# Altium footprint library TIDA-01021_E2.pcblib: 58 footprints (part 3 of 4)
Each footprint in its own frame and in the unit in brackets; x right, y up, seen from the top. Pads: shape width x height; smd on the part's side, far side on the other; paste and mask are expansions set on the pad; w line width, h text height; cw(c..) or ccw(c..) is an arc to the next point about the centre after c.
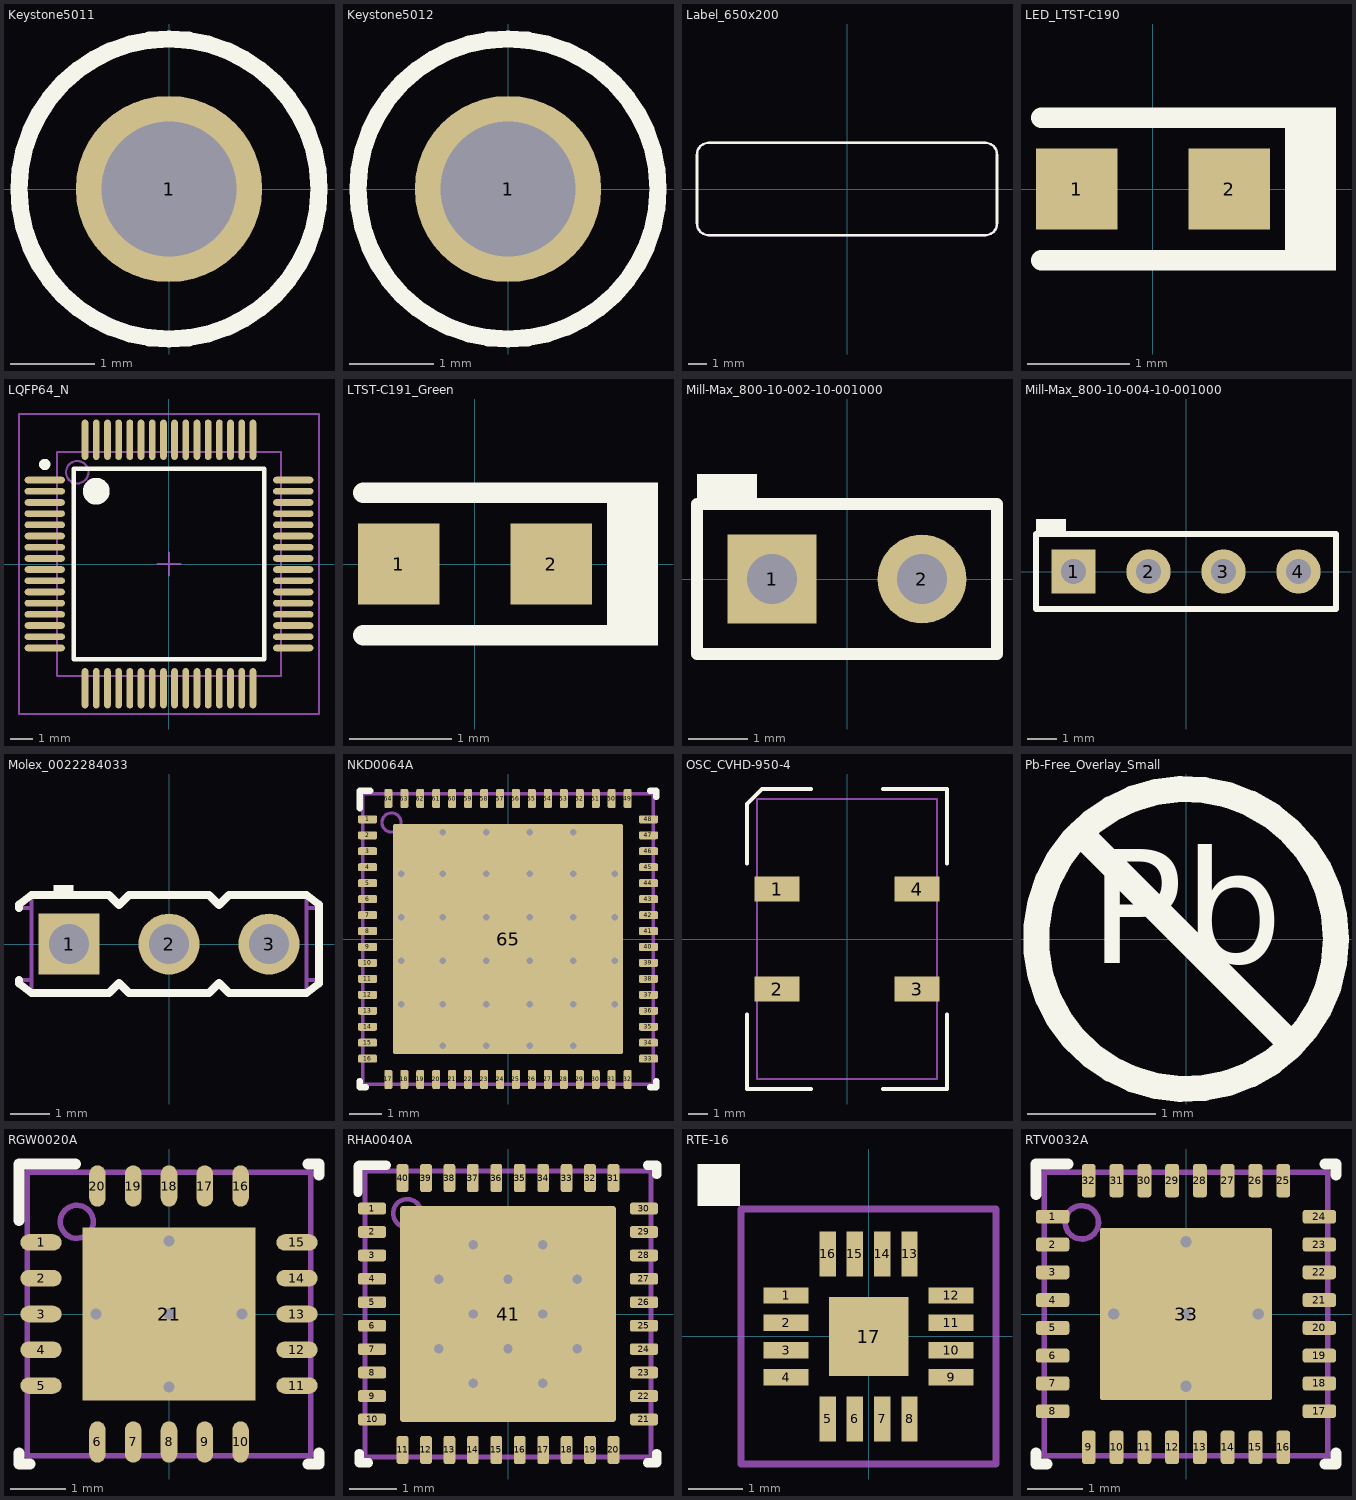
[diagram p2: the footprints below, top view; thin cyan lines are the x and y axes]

## Keystone5011 [mil] "Keystone Multipurpose loops"
height 320
pads (1):
  round 87 hole 63: 1(0,0)
Top Overlay:
  circle w7.99: c0,0 r70
Mechanical 5:
  circle w5: c0,0 r69.46
  text ".Designator" at 9.51,-35.02 h25
3D body "Keystone_5011.stp": height 318.9, standoff -125.98, extent -63,-63 62.74,62.49

## Keystone5012 [mil] "Keystone Multipurpose loops"
height 320
pads (1):
  round 87 hole 63: 1(0,0)
Top Overlay:
  circle w7.99: c0,0 r70
Mechanical 5:
  circle w5: c0,0 r69.46
  text ".Designator" at 37.32,14.4 h25
3D body "Keystone_5012.stp": height 318.9, standoff -125.98, extent -63,-63 62.74,62.49

## Label_650x200 [mil] "Thermal Transfer Label"
height 1
pads (1):
  round 1 on Mech13: 0(0,0)
Top Overlay:
  lines w5: -325,-75 ccw(c-300,-75) -300,-100 ; -325,75 cw(c-300,75) -300,100 ; 300,-100 ccw(c300,-75) 325,-75 ; 300,100 cw(c300,75) 325,75
  lines w6: -325,-75 -325,75 ; -300,-100 300,-100 ; -300,100 300,100 ; 325,-75 325,75
Mechanical 5:
  lines w5: -325,-75 ccw(c-300,-75) -300,-100 300,-100 ccw(c300,-75) 325,-75 325,75 ccw(c300,75) 300,100 -300,100 ccw(c-300,75) -325,75 -325,-75
  text ".Designator" at -60,-20 h25
3D body: height 1, standoff 0, extent -325.02,-100.02 325.02,100.02

## LED_LTST-C190 [mm] "Lite-On"
height 0.9
pads (2):
  rect 0.8x0.8 smd: 1(-0.75,0) 2(0.75,0)
Top Overlay:
  region: 1.8,0.8 1.3,0.8 1.3,-0.8 1.8,-0.8
  lines w0.2: -1.1,-0.7 1.4,-0.7 ; -1.1,0.7 1.4,0.7
Mechanical 5:
  region: 1.8,0.75 1.3,0.75 1.3,-0.75 1.8,-0.75
  lines w0.1: -1.1,-0.7 1.4,-0.7 ; -1.1,0.7 1.4,0.7
  text ".Designator" at 0.802,0.364 h0.64
3D body "Lite-On_LTST_C190.stp": height 0.9, standoff 0, extent -0.85,-0.45 0.85,0.45

## LQFP64_N [mm] "Thin QFP, 64-Leads, Body 10x10mm, Pitch 0.5mm, IPC Medium Density"
height 1.6
pads (64):
  oval 1.8x0.3 smd: 1(-5.55,3.75) 2(-5.55,3.25) 3(-5.55,2.75) 4(-5.55,2.25) 5(-5.55,1.75) 6(-5.55,1.25) 7(-5.55,0.75) 8(-5.55,0.25) 9(-5.55,-0.25) 10(-5.55,-0.75) 11(-5.55,-1.25) 12(-5.55,-1.75) 13(-5.55,-2.25) 14(-5.55,-2.75) 15(-5.55,-3.25) 16(-5.55,-3.75) 33(5.55,-3.75) 34(5.55,-3.25) 35(5.55,-2.75) 36(5.55,-2.25) 37(5.55,-1.75) 38(5.55,-1.25) 39(5.55,-0.75) 40(5.55,-0.25) 41(5.55,0.25) 42(5.55,0.75) 43(5.55,1.25) 44(5.55,1.75) 45(5.55,2.25) 46(5.55,2.75) 47(5.55,3.25) 48(5.55,3.75)
  oval 0.3x1.8 smd: 17(-3.75,-5.55) 18(-3.25,-5.55) 19(-2.75,-5.55) 20(-2.25,-5.55) 21(-1.75,-5.55) 22(-1.25,-5.55) 23(-0.75,-5.55) 24(-0.25,-5.55) 25(0.25,-5.55) 26(0.75,-5.55) 27(1.25,-5.55) 28(1.75,-5.55) 29(2.25,-5.55) 30(2.75,-5.55) 31(3.25,-5.55) 32(3.75,-5.55) 49(3.75,5.55) 50(3.25,5.55) 51(2.75,5.55) 52(2.25,5.55) 53(1.75,5.55) 54(1.25,5.55) 55(0.75,5.55) 56(0.25,5.55) 57(-0.25,5.55) 58(-0.75,5.55) 59(-1.25,5.55) 60(-1.75,5.55) 61(-2.25,5.55) 62(-2.75,5.55) 63(-3.25,5.55) 64(-3.75,5.55)
Top Overlay:
  circle w0.6: c-3.25,3.25 r0.3
  circle w0.25: c-5.55,4.45 r0.125
  lines w0.2: -4.25,-4.25 4.25,-4.25 4.25,4.25 -4.25,4.25 -4.25,-4.25
Mechanical 5:
  circle w0.1: c-4.1,4.1 r0.5
  lines w0.1: -5,-5 5,-5 5,5 -5,5 -5,-5
  text ".Designator" at 1.147,0.163 h0.64
Mechanical 15:
  lines w0.1: -0.5,0 0.5,0 ; 0,-0.5 0,0.5 ; -6.7,-6.7 6.7,-6.7 6.7,6.7 -6.7,6.7 -6.7,-6.7
3D body: height 1.6, standoff 0, extent -5,-5 5,5

## LTST-C191_Green [mm] "Lite-On"
height 0.65
pads (2):
  rect 0.8x0.8 smd: 1(-0.75,0) 2(0.75,0)
Top Overlay:
  region: 1.8,0.8 1.3,0.8 1.3,-0.8 1.8,-0.8
  lines w0.2: -1.1,-0.7 1.4,-0.7 ; -1.1,0.7 1.4,0.7
Mechanical 5:
  region: 1.8,0.75 1.3,0.75 1.3,-0.75 1.8,-0.75
  lines w0.1: -1.1,-0.7 1.4,-0.7 ; -1.1,0.7 1.4,0.7
  text ".Designator" at 0.419,0.373 h0.64
3D body: height 0.65, standoff 0.2, extent -0.624,-0.449 0.624,0.449
3D body: height 0.2, standoff 0, extent -0.849,-0.449 0.849,0.449

## Mill-Max_800-10-002-10-001000 [mm] "Mill-Max"
height 8.128
pads (2):
  rect 1.5x1.5 hole 0.85: 1(-1.27,0)
  round 1.5 hole 0.85: 2(1.27,0)
Top Overlay:
  rectangle: -2.54,1.27 -1.524,1.778
  lines w0.203: -2.54,-1.27 2.54,-1.27 2.54,1.27 -2.54,1.27 -2.54,-1.27
Mechanical 5:
  lines w0.102: -2.54,-1.27 -2.54,1.27 2.54,1.27 2.54,-1.27 -2.54,-1.27
  text ".Designator" at 0.362,0.73 h0.64
3D body: height 3.17, standoff 0, extent -2.539,-1.269 2.539,1.269
3D body: height 8.13, standoff 0, extent 0.892,-0.38 1.651,0.38
3D body: height 8.13, standoff 0, extent -1.648,-0.38 -0.889,0.38
3D body: height 0.81, standoff -3, extent 0.968,-0.304 1.575,0.304
3D body: height 0.81, standoff -3, extent -1.572,-0.304 -0.965,0.304

## Mill-Max_800-10-004-10-001000 [mm] "Mill-Max"
height 8.128
pads (4):
  rect 1.5x1.5 hole 0.85: 1(-3.81,0)
  round 1.5 hole 0.85: 2(-1.27,0) 3(1.27,0) 4(3.81,0)
Top Overlay:
  rectangle: -5.08,1.27 -4.064,1.778
  lines w0.203: -5.08,-1.27 -5.08,1.27 5.08,1.27 5.08,-1.27 -5.08,-1.27
Mechanical 5:
  lines w0.102: -5.08,-1.27 5.08,-1.27 5.08,1.27 -5.08,1.27 -5.08,-1.27
  text ".Designator" at 0.206,-0.787 h0.64
3D body: height 0.81, standoff -3, extent -4.112,-0.304 -3.505,0.304
3D body: height 0.81, standoff -3, extent -1.572,-0.304 -0.965,0.304
3D body: height 0.81, standoff -3, extent 0.968,-0.304 1.575,0.304
3D body: height 0.81, standoff -3, extent 3.508,-0.304 4.115,0.304
3D body: height 8.13, standoff 0, extent -4.188,-0.38 -3.429,0.38
3D body: height 8.13, standoff 0, extent -1.648,-0.38 -0.889,0.38
3D body: height 8.13, standoff 0, extent 0.892,-0.38 1.651,0.38
3D body: height 8.13, standoff 0, extent 3.432,-0.38 4.191,0.38
3D body: height 3.17, standoff 0, extent -5.079,-1.269 5.079,1.269

## Molex_0022284033 [mm] "Header, 2.54mm, 3x1, TH"
height 8.88
pads (3):
  rect 1.55x1.55 hole 1.02: 1(-2.54,0)
  round 1.55 hole 1.02: 2(0,0) 3(2.54,0)
Top Overlay:
  rectangle: -2.93,1.245 -2.43,1.5
  lines w0.2: -3.81,-0.914 -3.81,-1.003 -3.492,-1.245 -1.524,-1.245 -1.27,-0.991 -1.016,-1.245 1.016,-1.245 1.27,-0.991 1.524,-1.245 3.492,-1.245 3.81,-1.003 3.81,-0.914 3.81,0.914 3.81,1.003 3.492,1.245 1.524,1.245 1.27,0.991 1.016,1.245 -1.016,1.245 -1.27,0.991 -1.524,1.245 -3.492,1.245 -3.81,1.003 -3.81,0.914
Mechanical 5:
  lines w0.1: -3.492,-1.168 -3.492,1.168 ; -3.492,-0.914 -3.81,-0.914 -3.81,-1.003 -3.492,-1.245 -1.524,-1.245 -1.27,-0.991 -1.016,-1.245 1.016,-1.245 1.27,-0.991 1.524,-1.245 3.492,-1.245 3.81,-1.003 3.81,-0.914 ; -3.492,0.914 -3.81,0.914 -3.81,1.003 -3.492,1.245 -1.524,1.245 -1.27,0.991 -1.016,1.245 1.016,1.245 1.27,0.991 1.524,1.245 3.492,1.245 3.81,1.003 3.81,0.914 ; 3.492,-1.168 3.492,1.168 ; 3.492,-0.914 3.81,-0.914 ; 3.492,0.914 3.81,0.914 ; 3.81,-0.914 3.81,0.914
  text ".Designator" at 0.381,-0.914 h0.64
3D body "022284033.stp": height 8.4, standoff -3.16, extent -3.81,-1.244 3.81,1.245

## NKD0064A [mm] "QFN, 64-Leads, Body 9x9mm, Pitch 0.5mm"
height 0.8
pads (65):
  rrect40% 0.6x0.25 smd: 1(-4.4,3.75) 2(-4.4,3.25) 3(-4.4,2.75) 4(-4.4,2.25) 5(-4.4,1.75) 6(-4.4,1.25) 7(-4.4,0.75) 8(-4.4,0.25) 9(-4.4,-0.25) 10(-4.4,-0.75) 11(-4.4,-1.25) 12(-4.4,-1.75) 13(-4.4,-2.25) 14(-4.4,-2.75) 15(-4.4,-3.25) 16(-4.4,-3.75) 33(4.4,-3.75) 34(4.4,-3.25) 35(4.4,-2.75) 36(4.4,-2.25) 37(4.4,-1.75) 38(4.4,-1.25) 39(4.4,-0.75) 40(4.4,-0.25) 41(4.4,0.25) 42(4.4,0.75) 43(4.4,1.25) 44(4.4,1.75) 45(4.4,2.25) 46(4.4,2.75) 47(4.4,3.25) 48(4.4,3.75)
  rrect40% 0.25x0.6 smd: 17(-3.75,-4.4) 18(-3.25,-4.4) 19(-2.75,-4.4) 20(-2.25,-4.4) 21(-1.75,-4.4) 22(-1.25,-4.4) 23(-0.75,-4.4) 24(-0.25,-4.4) 25(0.25,-4.4) 26(0.75,-4.4) 27(1.25,-4.4) 28(1.75,-4.4) 29(2.25,-4.4) 30(2.75,-4.4) 31(3.25,-4.4) 32(3.75,-4.4) 49(3.75,4.4) 50(3.25,4.4) 51(2.75,4.4) 52(2.25,4.4) 53(1.75,4.4) 54(1.25,4.4) 55(0.75,4.4) 56(0.25,4.4) 57(-0.25,4.4) 58(-0.75,4.4) 59(-1.25,4.4) 60(-1.75,4.4) 61(-2.25,4.4) 62(-2.75,4.4) 63(-3.25,4.4) 64(-3.75,4.4)
  rrect1% 7.2x7.2 smd paste-3.6: 65(0,0)
via 0.68,0.68 diameter 0.5 hole 0.2
via -0.68,0.68 diameter 0.5 hole 0.2
via -0.68,-0.68 diameter 0.5 hole 0.2
via 0.68,-0.68 diameter 0.5 hole 0.2
via -2.04,0.68 diameter 0.5 hole 0.2
via 2.04,0.68 diameter 0.5 hole 0.2
via 2.04,-0.68 diameter 0.5 hole 0.2
via -2.04,-0.68 diameter 0.5 hole 0.2
via -2.04,-2.04 diameter 0.5 hole 0.2
via -0.68,-2.04 diameter 0.5 hole 0.2
via 0.68,-2.04 diameter 0.5 hole 0.2
via 2.04,-2.04 diameter 0.5 hole 0.2
via -2.04,2.04 diameter 0.5 hole 0.2
via -0.68,2.04 diameter 0.5 hole 0.2
via 0.68,2.04 diameter 0.5 hole 0.2
via 2.04,2.04 diameter 0.5 hole 0.2
via -2.04,3.35 diameter 0.5 hole 0.2
via -0.68,3.35 diameter 0.5 hole 0.2
via 0.68,3.35 diameter 0.5 hole 0.2
via 2.04,3.35 diameter 0.5 hole 0.2
via 0.68,-3.35 diameter 0.5 hole 0.2
via 2.04,-3.35 diameter 0.5 hole 0.2
via -0.68,-3.35 diameter 0.5 hole 0.2
via -2.04,-3.35 diameter 0.5 hole 0.2
via 3.35,-0.68 diameter 0.5 hole 0.2
via 3.35,-2.04 diameter 0.5 hole 0.2
via -3.35,-2.04 diameter 0.5 hole 0.2
via -3.35,-0.68 diameter 0.5 hole 0.2
via -3.35,2.04 diameter 0.5 hole 0.2
via -3.35,0.68 diameter 0.5 hole 0.2
via 3.35,2.04 diameter 0.5 hole 0.2
via 3.35,0.68 diameter 0.5 hole 0.2
Top Overlay:
  lines w0.2: -4.65,-4.45 -4.65,-4.65 -4.45,-4.65 ; -4.65,4.1 -4.65,4.65 -4.32,4.65 ; 4.45,-4.65 4.65,-4.65 4.65,-4.45 ; 4.45,4.65 4.65,4.65 4.65,4.45
Top Paste:
  rectangle: -0.58,-0.58 0.58,0.58
  rectangle: 0.78,-0.58 1.94,0.58
  rectangle: 2.14,-0.58 3.3,0.58
  rectangle: 0.78,0.78 1.94,1.94
  rectangle: 0.78,2.14 1.94,3.3
  rectangle: 2.14,2.14 3.3,3.3
  rectangle: 2.14,0.78 3.3,1.94
  rectangle: -0.58,0.78 0.58,1.94
  rectangle: -0.58,2.14 0.58,3.3
  rectangle: -1.94,2.14 -0.78,3.3
  rectangle: -3.3,2.14 -2.14,3.3
  rectangle: -3.3,0.78 -2.14,1.94
  rectangle: -1.94,0.78 -0.78,1.94
  rectangle: -1.94,-0.58 -0.78,0.58
  rectangle: -3.3,-0.58 -2.14,0.58
  rectangle: -3.3,-1.94 -2.14,-0.78
  rectangle: -1.94,-1.94 -0.78,-0.78
  rectangle: -0.58,-1.94 0.58,-0.78
  rectangle: 0.78,-1.94 1.94,-0.78
  rectangle: 2.14,-1.94 3.3,-0.78
  rectangle: 2.14,-3.3 3.3,-2.14
  rectangle: 0.78,-3.3 1.94,-2.14
  rectangle: -0.58,-3.3 0.58,-2.14
  rectangle: -1.94,-3.3 -0.78,-2.14
  rectangle: -3.3,-3.3 -2.14,-2.14
Mechanical 5:
  circle w0.1: c-3.65,3.65 r0.3
  lines w0.1: -4.55,-4.55 -4.55,4.55 4.55,4.55 4.55,-4.55 -4.55,-4.55
  text ".Designator" at -0.047,0.001 h0.64
3D body: height 0.8, standoff 0, extent -4.549,-4.549 4.549,4.549
3D body: height 0.81, standoff 0.5, extent -3.949,3.351 -3.351,3.949

## OSC_CVHD-950-4 [mil] "Crystek recommended land pattern 2011-02-22 Rev H"
height 210
pads (4):
  rect 90x50 smd: 1(-140,100) 2(-140,-100) 3(140,-100) 4(140,100)
Top Overlay:
  lines w7.87: -200,-151.18 -200,-300 -71.73,-300 ; -200,151.18 -200,270 -170,300 -71.73,300 ; 71.73,-300 200,-300 200,-151.18 ; 71.73,300 200,300 200,151.18
Mechanical 5:
  lines w4: -180,-280 -180,280 180,280 180,-280 -180,-280
  text ".Designator" at -50,-20 h30
3D body "Crystek_CVHD-950.stp": height 209.06, standoff -0.39, extent -179.84,-279.53 180,279.53

## Pb-Free_Overlay_Small [mm]
height 9.53
Top Overlay:
  circle w0.203: c0,0 r1.168
  lines w0.203: -0.826,0.826 0.826,-0.826
  text "Pb" at -0.752,-0.48 h1.52

## RGW0020A [mm] "QFN, 20-Leads, Body 5x5mm, Pitch 0.65mm, Thermal Pad 3.15x3.15mm, TI Recommended"
height 1
pads (21):
  oval 0.75x0.3 smd: 1(-2.325,1.3) 2(-2.325,0.65) 3(-2.325,0) 4(-2.325,-0.65) 5(-2.325,-1.3) 11(2.325,-1.3) 12(2.325,-0.65) 13(2.325,0) 14(2.325,0.65) 15(2.325,1.3)
  oval 0.3x0.75 smd: 6(-1.3,-2.325) 7(-0.65,-2.325) 8(0,-2.325) 9(0.65,-2.325) 10(1.3,-2.325) 16(1.3,2.325) 17(0.65,2.325) 18(0,2.325) 19(-0.65,2.325) 20(-1.3,2.325)
  rect 3.15x3.15 smd paste-1.575: 21(0,0)
via 0,-1.325 diameter 0.5 hole 0.2
via 1.325,0 diameter 0.5 hole 0.2
via 0,0 diameter 0.5 hole 0.2
via -1.325,0 diameter 0.5 hole 0.2
via 0,1.325 diameter 0.5 hole 0.2
Top Overlay:
  lines w0.2: -2.725,-2.525 -2.725,-2.725 -2.525,-2.725 ; -2.725,1.7 -2.725,2.725 -1.7,2.725 ; 2.525,-2.725 2.725,-2.725 2.725,-2.525 ; 2.525,2.725 2.725,2.725 2.725,2.525
Top Paste:
  rectangle: 0.1,-1.468 1.468,-0.1
  region: -0.1,-0.1 -1.468,-0.1 -1.468,-1.468 -0.1,-1.468
  region: -0.1,1.468 -1.468,1.468 -1.468,0.1 -0.1,0.1
  rectangle: 0.1,0.1 1.468,1.468
Mechanical 5:
  circle w0.1: c-1.675,1.675 r0.3
  lines w0.1: -2.575,-2.575 2.575,-2.575 2.575,2.575 -2.575,2.575 -2.575,-2.575
  text ".Designator" at -0.867,-0.358 h0.64
3D body: height 1, standoff 0, extent -2.575,-2.575 2.575,2.575
3D body: height 1.01, standoff 0.5, extent -1.974,1.376 -1.376,1.974

## RHA0040A [mm] "QFN, 40-Leads, Body 6x6mm, Pitch 0.5mm, Thermal Pad 4.6x4.6mm, TI Recommended"
height 1
pads (41):
  rrect40% 0.6x0.25 smd: 1(-2.9,2.25) 2(-2.9,1.75) 3(-2.9,1.25) 4(-2.9,0.75) 5(-2.9,0.25) 6(-2.9,-0.25) 7(-2.9,-0.75) 8(-2.9,-1.25) 9(-2.9,-1.75) 10(-2.9,-2.25) 21(2.9,-2.25) 22(2.9,-1.75) 23(2.9,-1.25) 24(2.9,-0.75) 25(2.9,-0.25) 26(2.9,0.25) 27(2.9,0.75) 28(2.9,1.25) 29(2.9,1.75) 30(2.9,2.25)
  rrect40% 0.25x0.6 smd: 11(-2.25,-2.9) 12(-1.75,-2.9) 13(-1.25,-2.9) 14(-0.75,-2.9) 15(-0.25,-2.9) 16(0.25,-2.9) 17(0.75,-2.9) 18(1.25,-2.9) 19(1.75,-2.9) 20(2.25,-2.9) 31(2.25,2.9) 32(1.75,2.9) 33(1.25,2.9) 34(0.75,2.9) 35(0.25,2.9) 36(-0.25,2.9) 37(-0.75,2.9) 38(-1.25,2.9) 39(-1.75,2.9) 40(-2.25,2.9)
  rrect2% 4.6x4.6 smd paste-2.3: 41(0,0)
via 0,-0.74 diameter 0.5 hole 0.2
via -1.48,-0.74 diameter 0.5 hole 0.2
via -0.74,0 diameter 0.5 hole 0.2
via 1.48,-0.74 diameter 0.5 hole 0.2
via 0.74,1.48 diameter 0.5 hole 0.2
via 1.48,0.74 diameter 0.5 hole 0.2
via -1.48,0.74 diameter 0.5 hole 0.2
via 0.74,0 diameter 0.5 hole 0.2
via -0.74,1.48 diameter 0.5 hole 0.2
via 0.74,-1.48 diameter 0.5 hole 0.2
via -0.74,-1.48 diameter 0.5 hole 0.2
via 0,0.74 diameter 0.5 hole 0.2
Top Overlay:
  lines w0.2: -3.2,2.6 -3.2,3.15 ; -3.175,-2.975 -3.175,-3.175 -2.975,-3.175 ; -3.175,3.175 -2.6,3.175 ; 2.975,-3.175 3.175,-3.175 3.175,-2.975 ; 2.975,3.175 3.175,3.175 3.175,2.975
Top Paste:
  rectangle: -0.64,-0.64 0.64,0.64
  rectangle: 0.84,-0.64 2.12,0.64
  region: -0.84,0.64 -2.12,0.64 -2.12,-0.64 -0.84,-0.64
  region: -0.84,2.12 -2.12,2.12 -2.12,0.84 -0.84,0.84
  rectangle: 0.84,0.84 2.12,2.12
  rectangle: -0.64,0.84 0.64,2.12
  rectangle: -0.64,-2.12 0.64,-0.84
  rectangle: 0.84,-2.12 2.12,-0.84
  region: -0.84,-0.84 -2.12,-0.84 -2.12,-2.12 -0.84,-2.12
Mechanical 5:
  circle w0.1: c-2.15,2.15 r0.3
  lines w0.1: -3.05,-3.05 3.05,-3.05 3.05,3.05 -3.05,3.05 -3.05,-3.05
  text ".Designator" at 0.264,0.121 h0.64
3D body "RHA0040A.stp": height 1, standoff 0, extent -3,-3 3,3

## RTE-16 [mil]
height 375.2
pads (17):
  rect 32.24x11.8 smd mask+1: 1(-59.45,29.55) 2(-59.45,9.85) 3(-59.45,-9.85) 4(-59.45,-29.55) 9(59.55,-29.55) 10(59.55,-9.85) 11(59.55,9.85) 12(59.55,29.55)
  rect 11.8x32.24 smd mask+1: 5(-29.5,-59.5) 6(-9.8,-59.5) 7(9.9,-59.5) 8(29.6,-59.5) 13(29.6,59.5) 14(9.9,59.5) 15(-9.8,59.5) 16(-29.5,59.5)
  rect 57.09x57.09 smd mask+1.18: 17(0.15,-0.05)
Top Overlay:
  region: -123.03,94.37 -93.03,94.37 -93.03,124.37 -123.03,124.37
Mechanical 5:
  lines w5: -92,-92 92,-92 92,92 -92,92 -92,-92
  text "*" at -82.68,51.18 h25
  text ".Designator" at 6,-29 h25

## RTV0032A [mm] "QFN, 32-Leads, Body 5x5mm, Pitch 0.5mm"
height 0.8
pads (33):
  rrect40% 0.6x0.25 smd: 1(-2.4,1.75) 2(-2.4,1.25) 3(-2.4,0.75) 4(-2.4,0.25) 5(-2.4,-0.25) 6(-2.4,-0.75) 7(-2.4,-1.25) 8(-2.4,-1.75) 17(2.4,-1.75) 18(2.4,-1.25) 19(2.4,-0.75) 20(2.4,-0.25) 21(2.4,0.25) 22(2.4,0.75) 23(2.4,1.25) 24(2.4,1.75)
  rrect40% 0.25x0.6 smd: 9(-1.75,-2.4) 10(-1.25,-2.4) 11(-0.75,-2.4) 12(-0.25,-2.4) 13(0.25,-2.4) 14(0.75,-2.4) 15(1.25,-2.4) 16(1.75,-2.4) 25(1.75,2.4) 26(1.25,2.4) 27(0.75,2.4) 28(0.25,2.4) 29(-0.25,2.4) 30(-0.75,2.4) 31(-1.25,2.4) 32(-1.75,2.4)
  rrect3% 3.1x3.1 smd paste-1.55: 33(0,0)
via 0,1.3 diameter 0.5 hole 0.2
via -1.3,0 diameter 0.5 hole 0.2
via 0,0 diameter 0.5 hole 0.2
via 1.3,0 diameter 0.5 hole 0.2
via 0,-1.3 diameter 0.5 hole 0.2
Top Overlay:
  lines w0.2: -2.7,-2.5 -2.7,-2.7 -2.5,-2.7 ; -2.7,2.15 -2.7,2.7 -2.125,2.7 ; 2.5,-2.7 2.7,-2.7 2.7,-2.5 ; 2.5,2.7 2.7,2.7 2.7,2.5
Top Paste:
  rectangle: 0.1,0.1 1.4,1.4
  region: -0.1,1.4 -1.4,1.4 -1.4,0.1 -0.1,0.1
  region: -0.1,-0.1 -1.4,-0.1 -1.4,-1.4 -0.1,-1.4
  rectangle: 0.1,-1.4 1.4,-0.1
Mechanical 5:
  circle w0.1: c-1.875,1.65 r0.3
  lines w0.1: -2.55,-2.55 -2.55,2.55 2.55,2.55 2.55,-2.55 -2.55,-2.55
  text ".Designator" at -1.524,-0.508 h0.64
3D body: height 0.8, standoff 0, extent -2.55,-2.55 2.55,2.55
3D body: height 0.81, standoff 0.5, extent -2.174,1.351 -1.576,1.949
